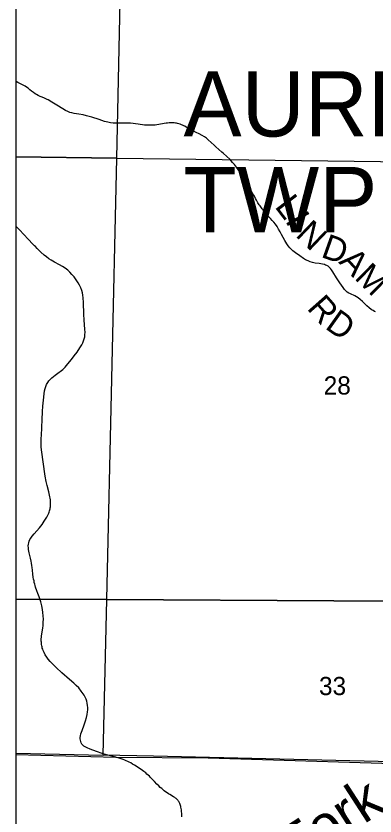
# Model space of a CAD drawing. Extents: x 0 to 34, y 0 to 22.
# Drawn here: x 2.1 to 2.925, y 15.933 to 17.772 of the extents above; entities that cross this region are included whole.
import ezdxf

# ---------------------------------------------------------------- set-up
doc = ezdxf.new("R2010")
doc.units = 0
for name, color, linetype in [('GM_X_Corporation', 7, 'Continuous'), ('GM_X_Major_River_Text', 7, 'Continuous'), ('GM_X_Section_Text', 7, 'Continuous'), ('GM_X_Township_Road', 7, 'Continuous'), ('GM_X_Township_Road_Text', 7, 'Continuous'), ('GM_X_Township_Text', 7, 'Continuous'), ('SH_Data', 7, 'Continuous'), ('SH_Text', 7, 'Continuous')]:
    doc.layers.add(name, color=color, linetype=linetype)

msp = doc.modelspace()

# ---------------------------------------------------------------- linework, layer by layer
at = {"layer": 'GM_X_Corporation'}
msp.add_lwpolyline([(4.6584, 17.4085), (4.4004, 17.4134), (4.4034, 17.9703), (4.4042, 18.3894), (4.0024, 18.3976), (3.4726, 18.3965), (3.3689, 18.3973), (3.3767, 18.6788), (3.3859, 18.705), (3.3893, 18.721), (3.3872, 18.7823), (3.3779, 18.9241), (3.3711, 18.9531), (3.3709, 19.4088), (3.3147, 19.4093), (2.7824, 19.4152), (2.1, 19.4241), (2.1, 14.1)], dxfattribs=at)
for points in [[(2.1, 18.4215), (2.1, 17.4478), (2.3314, 17.4451), (2.3525, 18.417)], [(2.1, 17.4478), (2.1, 16.4314), (2.3088, 16.4308), (2.3314, 17.4451)], [(2.3314, 17.4451), (3.3626, 17.4322), (3.3525, 16.4245), (2.3088, 16.4308)], [(2.1, 16.4314), (2.1, 16.0777), (2.3002, 16.073), (2.3088, 16.4308)], [(2.3088, 16.4308), (3.3525, 16.4245), (3.3513, 16.0482), (2.4158, 16.0704), (2.3002, 16.073)]]:
    msp.add_lwpolyline(points, close=True, dxfattribs=at)
at = {"layer": 'GM_X_Township_Road'}
for points in [[(2.9261, 17.0919), (2.9238, 17.0929), (2.9211, 17.0945), (2.9188, 17.0959), (2.9164, 17.0975), (2.9115, 17.1013), (2.9068, 17.1054), (2.8966, 17.1154), (2.8912, 17.1204), (2.8868, 17.1239), (2.8827, 17.1266), (2.8788, 17.1287), (2.8691, 17.1328), (2.8652, 17.1347), (2.8615, 17.1371), (2.8582, 17.1399), (2.8552, 17.143), (2.8518, 17.1474), (2.8444, 17.1582), (2.8369, 17.1696), (2.8285, 17.1834), (2.8254, 17.1881), (2.8227, 17.1915), (2.8201, 17.1942), (2.8172, 17.1965), (2.8146, 17.1981), (2.8118, 17.1994), (2.8088, 17.2004), (2.8046, 17.2014), (2.7972, 17.2025), (2.7874, 17.2039), (2.7819, 17.205), (2.7765, 17.2067), (2.7714, 17.2088), (2.7658, 17.2116), (2.7612, 17.2143), (2.7522, 17.2202), (2.7422, 17.2275), (2.7362, 17.2322), (2.7323, 17.2357), (2.7291, 17.2391), (2.7258, 17.2433), (2.7225, 17.2481), (2.7181, 17.2556), (2.7105, 17.2694), (2.7072, 17.2757), (2.7037, 17.2821), (2.7003, 17.2878), (2.6967, 17.2929), (2.6927, 17.2976), (2.689, 17.3017), (2.6848, 17.3063), (2.681, 17.3103), (2.6778, 17.3139), (2.6744, 17.318), (2.6712, 17.3219), (2.6679, 17.3261), (2.6661, 17.3283), (2.664, 17.3311), (2.6611, 17.3351), (2.659, 17.338), (2.6562, 17.3422), (2.6552, 17.344), (2.6528, 17.3483), (2.6507, 17.3523), (2.6487, 17.3558), (2.6464, 17.3599), (2.644, 17.364), (2.6412, 17.3688), (2.638, 17.3741), (2.6355, 17.3783), (2.6329, 17.3825), (2.6303, 17.3868), (2.627, 17.392), (2.6219, 17.4004), (2.612, 17.4164), (2.6069, 17.424), (2.6022, 17.4303), (2.5979, 17.4354), (2.5921, 17.4416), (2.5837, 17.4495), (2.577, 17.4556), (2.573, 17.459), (2.5592, 17.4714), (2.5556, 17.4748), (2.5419, 17.4873), (2.5376, 17.4909), (2.533, 17.4941), (2.5277, 17.4974), (2.5211, 17.5009), (2.514, 17.5042), (2.5092, 17.5063), (2.5054, 17.5082), (2.5016, 17.51), (2.4982, 17.512), (2.4908, 17.5165), (2.488, 17.5182), (2.4854, 17.5196), (2.4831, 17.5206), (2.4803, 17.5219), (2.4773, 17.5229), (2.4744, 17.5239), (2.4716, 17.5247), (2.469, 17.5253), (2.4667, 17.5258), (2.4638, 17.5262), (2.461, 17.5264), (2.4579, 17.5264), (2.455, 17.5264), (2.4517, 17.5261), (2.4484, 17.5257), (2.4449, 17.5253), (2.424, 17.5219), (2.42, 17.5212), (2.416, 17.5209), (2.4127, 17.5206), (2.4092, 17.5205), (2.403, 17.5205), (2.3956, 17.5211), (2.3808, 17.5229), (2.3629, 17.5251), (2.3555, 17.5257), (2.3486, 17.5258), (2.3381, 17.5254), (2.3294, 17.5253), (2.3232, 17.5256), (2.317, 17.5264), (2.3109, 17.5276), (2.3037, 17.5295), (2.2913, 17.5335), (2.2742, 17.5391), (2.2622, 17.5426), (2.2544, 17.5444), (2.2446, 17.5462), (2.2335, 17.5479), (2.2281, 17.5489), (2.2239, 17.5501), (2.2193, 17.552), (2.2138, 17.5548), (2.2079, 17.5583), (2.1942, 17.5668), (2.1825, 17.5739), (2.1739, 17.5788), (2.1717, 17.58), (2.1689, 17.5815), (2.1656, 17.583), (2.1598, 17.5853), (2.1558, 17.587), (2.1513, 17.589), (2.1475, 17.591), (2.1443, 17.5928), (2.1402, 17.5957), (2.1359, 17.5993), (2.1321, 17.6023), (2.1286, 17.6049), (2.1261, 17.6067), (2.121, 17.6101), (2.1181, 17.6117), (2.1152, 17.6133), (2.1085, 17.6168), (2.1044, 17.619), (2.1002, 17.6213), (2.1, 17.6214)], [(2.159, 16.8224), (2.1592, 16.8265), (2.1601, 16.8432), (2.1611, 16.8629), (2.1618, 16.8752), (2.1629, 16.8888), (2.1645, 16.9036), (2.1656, 16.9103), (2.1669, 16.9157), (2.1684, 16.9204), (2.1704, 16.9249), (2.1729, 16.9292), (2.1757, 16.9332), (2.1785, 16.9364), (2.1825, 16.9403), (2.19, 16.9464), (2.1993, 16.9532), (2.2019, 16.955), (2.2048, 16.9572), (2.2073, 16.9593), (2.2101, 16.9616), (2.2127, 16.9645), (2.2158, 16.9685), (2.219, 16.9724), (2.2272, 16.9822), (2.2338, 16.9904), (2.2404, 16.9994), (2.247, 17.0092), (2.2512, 17.016), (2.2535, 17.0204), (2.2555, 17.025), (2.257, 17.0297), (2.258, 17.0345), (2.2585, 17.0394), (2.2587, 17.0444), (2.2583, 17.0518), (2.2566, 17.0723), (2.2559, 17.0865), (2.2552, 17.1133), (2.2545, 17.1238), (2.2537, 17.13), (2.2525, 17.1354), (2.251, 17.1408), (2.2488, 17.1466), (2.2459, 17.1528), (2.2426, 17.1588), (2.2382, 17.1656), (2.2334, 17.1721), (2.2286, 17.1778), (2.2239, 17.1827), (2.2188, 17.1872), (2.2129, 17.1918), (2.2072, 17.1956), (2.2003, 17.1998), (2.1888, 17.2059), (2.1808, 17.2105), (2.1755, 17.2139), (2.17, 17.2179), (2.1647, 17.2222), (2.1574, 17.2289), (2.1486, 17.2376), (2.1447, 17.2416), (2.1424, 17.2437), (2.1389, 17.2473), (2.1283, 17.2586), (2.1083, 17.2799), (2.1, 17.2884)], [(2.3304, 16.0677), (2.3296, 16.0679), (2.3078, 16.0738), (2.2977, 16.0769), (2.2848, 16.0813), (2.2702, 16.0867), (2.2633, 16.0895), (2.2588, 16.0917), (2.2558, 16.0938), (2.2535, 16.096), (2.2516, 16.0984), (2.25, 16.101), (2.2487, 16.1039), (2.248, 16.1069), (2.2476, 16.11), (2.2477, 16.1137), (2.2482, 16.1174), (2.2493, 16.1216), (2.2522, 16.1298), (2.2567, 16.1421), (2.2599, 16.1515), (2.2621, 16.1593), (2.2636, 16.1659), (2.2645, 16.1721), (2.2649, 16.177), (2.2649, 16.182), (2.2645, 16.1869), (2.2637, 16.1919), (2.2625, 16.1967), (2.261, 16.2014), (2.259, 16.206), (2.2567, 16.2104), (2.2544, 16.2141), (2.25, 16.2201), (2.2441, 16.2273), (2.2386, 16.2332), (2.2332, 16.2383), (2.2233, 16.2469), (2.2054, 16.2622), (2.1925, 16.2739), (2.1844, 16.2816), (2.1785, 16.288), (2.1741, 16.2932), (2.1705, 16.2983), (2.1673, 16.3036), (2.1648, 16.3086), (2.1626, 16.3137), (2.1614, 16.3165), (2.1605, 16.319), (2.1599, 16.3214), (2.1593, 16.3242), (2.1589, 16.3269), (2.1585, 16.33), (2.1583, 16.3325), (2.1581, 16.3349), (2.1581, 16.3375), (2.1582, 16.3405), (2.1585, 16.3439), (2.1589, 16.3473), (2.1617, 16.3645), (2.1624, 16.3707), (2.1628, 16.3781), (2.163, 16.3855), (2.1627, 16.393), (2.1619, 16.401), (2.1609, 16.4078), (2.1591, 16.4163), (2.1568, 16.4253), (2.1532, 16.4366), (2.1503, 16.4446), (2.1481, 16.4506), (2.1452, 16.4588), (2.1439, 16.4627), (2.143, 16.466), (2.142, 16.4697), (2.1414, 16.4732), (2.1406, 16.4775), (2.1398, 16.4817), (2.1389, 16.4885), (2.1377, 16.4977), (2.137, 16.5038), (2.1363, 16.5088), (2.1355, 16.5137), (2.1347, 16.5185), (2.1335, 16.5253), (2.132, 16.5319), (2.1306, 16.538), (2.1289, 16.5452), (2.1284, 16.5495), (2.1283, 16.5538), (2.1286, 16.5575), (2.1293, 16.5611), (2.1303, 16.5647), (2.1318, 16.5681), (2.1339, 16.5719), (2.1368, 16.5759), (2.1416, 16.5816), (2.1538, 16.5955), (2.1599, 16.6033), (2.1648, 16.6103), (2.1708, 16.6196), (2.1734, 16.6245), (2.1754, 16.6289), (2.1764, 16.6316), (2.1772, 16.6342), (2.1778, 16.6363), (2.1784, 16.6389), (2.1789, 16.6413), (2.1792, 16.6438), (2.1794, 16.6462), (2.1796, 16.6487), (2.1796, 16.6514), (2.1795, 16.6536), (2.1793, 16.6572), (2.179, 16.6598), (2.1784, 16.6635), (2.1778, 16.6665), (2.1752, 16.6779), (2.1713, 16.6929), (2.1693, 16.7019), (2.167, 16.7141), (2.1622, 16.7472), (2.159, 16.7693), (2.1579, 16.7809), (2.1575, 16.7889), (2.1576, 16.7976), (2.1583, 16.8111), (2.159, 16.8224)], [(2.4812, 15.9311), (2.4809, 15.9383), (2.4805, 15.9435), (2.4802, 15.9468), (2.4797, 15.9503), (2.4791, 15.9529), (2.4786, 15.9551), (2.478, 15.9573), (2.4774, 15.9593), (2.4766, 15.9615), (2.4757, 15.9633), (2.4749, 15.9649), (2.4742, 15.9661), (2.4729, 15.968), (2.4717, 15.9696), (2.4698, 15.9716), (2.4681, 15.973), (2.4667, 15.9742), (2.4652, 15.9753), (2.4636, 15.9763), (2.462, 15.9772), (2.4534, 15.9822), (2.4505, 15.984), (2.4471, 15.9862), (2.4433, 15.9888), (2.4406, 15.991), (2.4373, 15.9937), (2.4349, 15.9958), (2.4317, 15.9987), (2.4281, 16.0022), (2.424, 16.0064), (2.4182, 16.0124), (2.4095, 16.0213), (2.4066, 16.0242), (2.4041, 16.0265), (2.4011, 16.0293), (2.3981, 16.0318), (2.3939, 16.035), (2.3907, 16.0375), (2.3854, 16.0411), (2.3815, 16.0439), (2.376, 16.0476), (2.3722, 16.05), (2.3681, 16.0524), (2.3636, 16.055), (2.3603, 16.0568), (2.357, 16.0584), (2.3535, 16.0601), (2.3501, 16.0614), (2.3461, 16.0629), (2.3419, 16.0643), (2.337, 16.0658), (2.3312, 16.0675), (2.3304, 16.0677)]]:
    msp.add_lwpolyline(points, dxfattribs=at)
at = {"layer": 'GM_X_Township_Text'}
msp.add_lwpolyline([(2.1, 19.4241), (2.1, 16.074), (2.3294, 16.0685), (2.5414, 16.0663), (3.0911, 16.0497), (3.9428, 16.0275), (4.0565, 16.0246), (4.383, 16.0223), (4.3994, 17.3911), (4.4004, 17.4134)], dxfattribs=at)
at = {"layer": 'SH_Data'}
msp.add_line((2.1, 20.9), (2.1, 14.1), dxfattribs=at)
at = {"layer": 'SH_Text'}
msp.add_lwpolyline([(2.1, 16.074), (2.1, 14.1), (6.4323, 14.1)], dxfattribs=at)

# ---------------------------------------------------------------- texts
at = {"layer": 'GM_X_Major_River_Text'}
msp.add_text('Fork', height=0.0947, rotation=32.9054, dxfattribs=at).set_placement((2.7401, 15.8102))
at = {"layer": 'GM_X_Section_Text'}
for s, p in [('28', (2.8073, 16.9017)), ('33', (2.7965, 16.2108))]:
    msp.add_text(s, height=0.04186, rotation=0, dxfattribs=at).set_placement(p)
at = {"layer": 'GM_X_Township_Road_Text'}
for s, rotation, p in [('L', 307.3593, (2.6932, 17.3335)), ('I', 299.3169, (2.7179, 17.3014)), ('N', 316.4091, (2.7406, 17.2665)), ('D', 340.4044, (2.7988, 17.2185)), ('A', 314.1474, (2.8402, 17.2055)), ('M', 315.7458, (2.8762, 17.1684)), ('R', 311.4485, (2.7669, 17.0991)), ('D', 324.5887, (2.8082, 17.0548))]:
    msp.add_text(s, height=0.0568, rotation=rotation, dxfattribs=at).set_placement(p)
at = {"layer": 'GM_X_Township_Text'}
for s, p in [('AURELIUS', (2.485, 17.4948)), ('TWP', (2.485, 17.2748))]:
    msp.add_text(s, height=0.15, rotation=0, dxfattribs=at).set_placement(p)

doc.saveas('drawing.dxf')
